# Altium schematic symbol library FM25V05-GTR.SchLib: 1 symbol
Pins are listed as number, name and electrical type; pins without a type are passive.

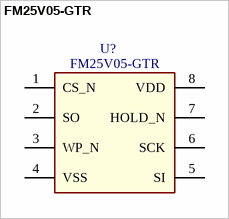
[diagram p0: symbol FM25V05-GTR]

## FM25V05-GTR
designator U?
4-Kbit (512 × 8) Serial (SPI) F-RAM; Manufacturer: Infineon Technologies
footprint SOIC127P602X173-8N-1-V (SOIC,1.27mm pitch;8 pin,3.899mm W X 4.889mm L X 1.727mm H body)
pins: 1 CS_N "Chip Select", 2 SO "Serial Output", 3 WP_N "Write Protect", 4 VSS "Ground for the device. Must be connected to the ground of the system", 5 SI "Serial Input", 6 SCK "Serial Clock", 7 HOLD_N "The HOLD pin is used when the host CPU must interrupt a memory operation for another  task.", 8 VDD "Power supply input to the device."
